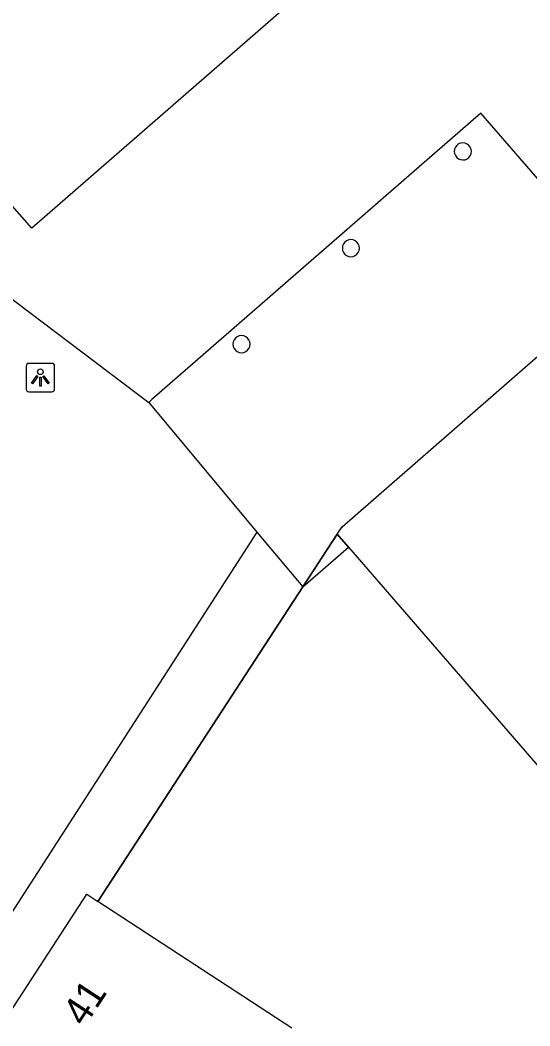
# Model space of a CAD drawing. Extents: x 155640 to 156810, y 382822 to 384046.
# Drawn here: x 156473.07 to 156490.98, y 383754.11 to 383789.39 of the extents above; entities that cross this region are included whole.
import ezdxf

# ---------------------------------------------------------------- set-up
doc = ezdxf.new("R2010")
doc.units = 0
for name, color, linetype in [('IMGEO_Lichtpunt', 7, 'Continuous'), ('IMGEO_Lijnafwatering', 7, 'Continuous'), ('IMGEO_Muur', 7, 'Continuous'), ('IMGEO_Pand', 7, 'Continuous'), ('IMGEO_Pand_nummerreeks', 7, 'Continuous'), ('IMGEO_Pand_overbouw', 7, 'Continuous'), ('IMGEO_Voetgangersgebied_open', 7, 'Continuous'), ('IMGEO_Voetpad_open', 7, 'Continuous')]:
    doc.layers.add(name, color=color, linetype=linetype)

msp = doc.modelspace()

# ---------------------------------------------------------------- linework, layer by layer
at = {"layer": 'IMGEO_Lichtpunt'}
for p, q in [((156473.287, 383777.257), (156473.287, 383776.45)), ((156473.287, 383777.257), (156473.287, 383776.45)), ((156474.189, 383777.352), (156473.381, 383777.352)), ((156474.189, 383777.352), (156473.381, 383777.352)), ((156474.283, 383776.45), (156474.283, 383777.257)), ((156474.283, 383776.45), (156474.283, 383777.257)), ((156473.381, 383776.356), (156474.189, 383776.356)), ((156473.381, 383776.356), (156474.189, 383776.356))]:
    msp.add_line(p, q, dxfattribs=at)
for points in [[(156473.661, 383776.921), (156473.7, 383776.893), (156473.512, 383776.631), (156473.474, 383776.658), (156473.661, 383776.921)], [(156473.873, 383776.893), (156473.911, 383776.92), (156474.098, 383776.658), (156474.059, 383776.63), (156473.873, 383776.893)], [(156473.763, 383776.873), (156473.81, 383776.873), (156473.81, 383776.551), (156473.763, 383776.551), (156473.763, 383776.873)]]:
    msp.add_lwpolyline(points, dxfattribs=at)
msp.add_circle((156473.786, 383777.055), 0.0994, dxfattribs=at)
for centre, start, end in [((156473.381, 383777.257), 90, 180), ((156473.381, 383777.257), 90, 180), ((156474.189, 383777.257), 0, 90), ((156474.189, 383777.257), 0, 90), ((156473.381, 383776.45), 180, 270), ((156473.381, 383776.45), 180, 270), ((156474.189, 383776.45), 270, 0), ((156474.189, 383776.45), 270, 360)]:
    msp.add_arc(centre, 0.0946, start, end, dxfattribs=at)
at = {"layer": 'IMGEO_Lijnafwatering'}
msp.add_lwpolyline([(156481.391, 383771.435), (156471.067, 383755.451)], dxfattribs=at)
at = {"layer": 'IMGEO_Muur'}
for points in [[(156484.208, 383771.362), (156483.001, 383769.51)], [(156483.001, 383769.51), (156475.806, 383758.471)]]:
    msp.add_lwpolyline(points, dxfattribs=at)
at = {"layer": 'IMGEO_Pand'}
for points in [[(156502.946, 383814.998), (156503.408, 383814.467), (156496.224, 383808.207), (156499.367, 383804.6), (156473.48, 383782.1), (156463.557, 383793.358)], [(156484.208, 383771.362), (156484.378, 383771.622), (156494.004, 383780.006), (156497.967, 383775.43)], [(156484.208, 383771.362), (156484.606, 383770.903)], [(156484.606, 383770.903), (156491.34, 383763.141)], [(156472.251, 383753.89), (156475.417, 383758.73), (156475.806, 383758.471)], [(156482.61, 383754.028), (156475.806, 383758.471)]]:
    msp.add_lwpolyline(points, dxfattribs=at)
for centre, radius, start, end in [((156488.62, 383784.788), 0.299, 119.9411, 240.0589), ((156488.621, 383784.787), 0.3, 359.9633, 120), ((156488.622, 383784.786), 0.299, 239.7135, 0.1322), ((156484.689, 383781.394), 0.299, 119.9411, 240.0589), ((156484.69, 383781.394), 0.3, 359.9633, 120), ((156484.691, 383781.393), 0.299, 239.7135, 0.1322), ((156480.848, 383778.026), 0.3, 359.9633, 120), ((156480.847, 383778.027), 0.299, 119.9411, 240.0589), ((156480.849, 383778.025), 0.299, 239.7135, 0.1322)]:
    msp.add_arc(centre, radius, start, end, dxfattribs=at)
at = {"layer": 'IMGEO_Pand_overbouw'}
msp.add_lwpolyline([(156522.244, 383748.131), (156489.331, 383786.036), (156489.254, 383786.124), (156477.703, 383776.08), (156477.589, 383775.981), (156481.391, 383771.435), (156483.001, 383769.51), (156484.606, 383770.903), (156484.208, 383771.362), (156484.378, 383771.622), (156494.004, 383780.006), (156497.967, 383775.43), (156496.178, 383773.878), (156499.415, 383770.147), (156491.34, 383763.141), (156495.141, 383758.761), (156496.961, 383761.545), (156504.403, 383768.001), (156526.125, 383742.921)], dxfattribs=at)
at = {"layer": 'IMGEO_Voetgangersgebied_open'}
msp.add_lwpolyline([(156471.098, 383780.883), (156477.589, 383775.981)], dxfattribs=at)
at = {"layer": 'IMGEO_Voetpad_open'}
for points in [[(156517.613, 383674.051), (156518.79, 383682.442), (156518.138, 383682.533), (156525.621, 383736.263), (156526.284, 383736.173), (156527.289, 383743.325), (156522.761, 383748.566), (156522.244, 383748.131), (156489.331, 383786.036), (156489.254, 383786.124), (156477.703, 383776.08), (156477.589, 383775.981)], [(156477.589, 383775.981), (156481.391, 383771.435), (156483.001, 383769.51)], [(156483.001, 383769.51), (156484.208, 383771.362)], [(156483.001, 383769.51), (156484.606, 383770.903)], [(156475.806, 383758.471), (156483.001, 383769.51)]]:
    msp.add_lwpolyline(points, dxfattribs=at)

# ---------------------------------------------------------------- texts
at = {"layer": 'IMGEO_Pand_nummerreeks'}
msp.add_text('41', height=1, rotation=56.8088, dxfattribs=at).set_placement((156475.34, 383754.045))

doc.saveas('drawing.dxf')
